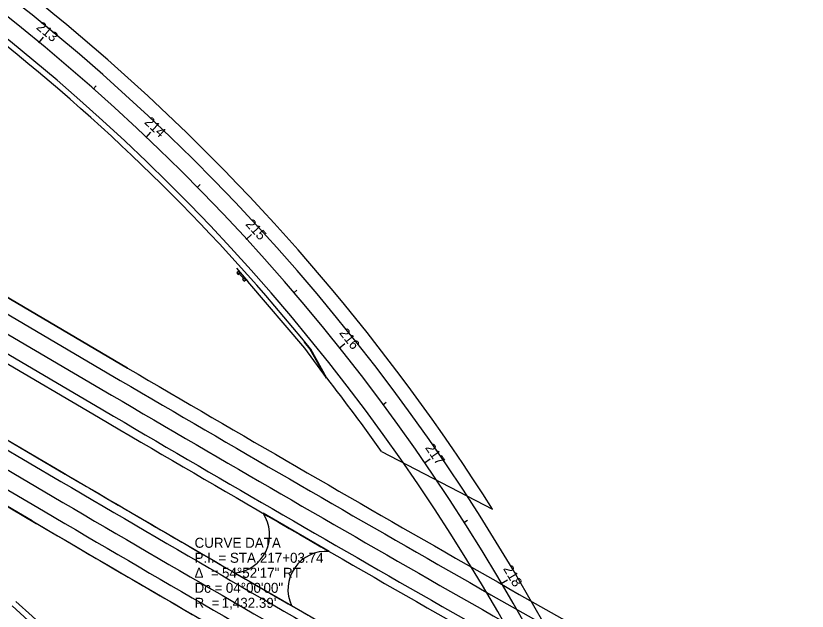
# Model space of a CAD drawing. Extents: x 76539 to 88870, y 518807 to 527554.
# Drawn here: x 87208 to 87761, y 522669 to 523086 of the extents above; entities that cross this region are included whole.
import ezdxf

# ---------------------------------------------------------------- set-up
doc = ezdxf.new("R2010")
doc.units = 0
for name, color, linetype in [('GE_P_Alignment_100_Curve_Data', 7, 'Continuous'), ('GE_P_Alignment_100_Stations', 7, 'Continuous'), ('PM_P_Edge_Line', 7, 'Continuous'), ('PM_P_Lane_Line', 7, 'Continuous'), ('PV_P_Shoulder', 7, 'Continuous'), ('RD_P_GR_Lt', 7, 'Continuous'), ('XS_P_Pavt_Surface', 7, 'Continuous')]:
    doc.layers.add(name, color=color, linetype=linetype)

msp = doc.modelspace()

# ---------------------------------------------------------------- linework, layer by layer
at = {"layer": 'GE_P_Alignment_100_Stations'}
for p, q in [((87224.3, 523066.94), (87227.48, 523070.8)), ((87262.32, 523034.48), (87264.31, 523036.72)), ((87299.19, 523000.71), (87302.64, 523004.34)), ((87334.86, 522965.67), (87337, 522967.78)), ((87369.29, 522929.41), (87372.97, 522932.79)), ((87402.43, 522891.98), (87404.71, 522893.93)), ((87434.24, 522853.4), (87438.15, 522856.52)), ((87464.68, 522813.75), (87467.1, 522815.53)), ((87493.73, 522773.05), (87497.85, 522775.88)), ((87521.33, 522731.36), (87523.86, 522732.98)), ((87547.47, 522688.74), (87551.77, 522691.28))]:
    msp.add_line(p, q, dxfattribs=at)
at = {"layer": 'PM_P_Edge_Line'}
for p, q in [((86028.65, 523566.61), (87281.21, 522830.81)), ((86016.49, 523545.92), (87269.05, 522810.12)), ((86962.35, 522923.05), (87239.68, 522760.13)), ((86950.19, 522902.35), (87227.53, 522739.44))]:
    msp.add_line(p, q, dxfattribs=at)
for centre, radius, start, end in [((86313.45, 521961.45), 1444.39, 9.23728, 64.10866), ((86313.45, 521961.45), 1444.39, 9.23728, 64.10866), ((86313.45, 521961.45), 1420.39, 9.24998, 64.10866), ((98861.51, 542544.07), 22862.98, 239.568441, 240.940285), ((98861.51, 542544.07), 22886.98, 239.568441, 240.940285), ((98861.51, 542544.07), 22944.95, 239.568441, 240.940516), ((98861.51, 542544.07), 22968.95, 239.568441, 240.940516), ((86249.47, 521595.47), 1440.6, 9.83522, 48.42092)]:
    msp.add_arc(centre, radius, start, end, dxfattribs=at)
at = {"layer": 'PM_P_Lane_Line'}
for p, q in [((86022.57, 523556.26), (87275.13, 522820.47)), ((86956.27, 522912.7), (87233.61, 522749.78))]:
    msp.add_line(p, q, dxfattribs=at)
for centre, radius, start, end in [((86313.45, 521961.45), 1432.72, 9.23728, 64.10866), ((98861.51, 542544.07), 22874.98, 239.568441, 240.940285), ((98861.51, 542544.07), 22956.95, 239.568441, 240.940516)]:
    msp.add_arc(centre, radius, start, end, dxfattribs=at)
at = {"layer": 'PV_P_Shoulder'}
for p, q in [((86033.71, 523575.23), (87286.27, 522839.43)), ((86013.45, 523540.74), (87266.01, 522804.95)), ((86965.39, 522928.22), (87242.72, 522765.3)), ((86945.13, 522893.73), (87222.46, 522730.81)), ((87409.82, 522857.4), (87410.22, 522857.7)), ((87414.19, 522852.82), (87425.45, 522832.61)), ((87425.04, 522832.33), (87425.45, 522832.61)), ((87427.16, 522711.16), (87380.97, 522737.86)), ((87361.24, 522696.16), (87400.87, 522673.25))]:
    msp.add_line(p, q, dxfattribs=at)
for points in [[(87409.82, 522857.4), (87413.78, 522852.53), (87425.02, 522832.37)], [(87425.45, 522832.61), (87414.19, 522852.82), (87410.21, 522857.71)]]:
    msp.add_lwpolyline(points, dxfattribs=at)
for centre, radius, start, end in [((86313.45, 521961.45), 1454.39, 32.40267, 64.10866), ((86313.45, 521961.45), 1416.39, 39.00003, 64.10866), ((98861.51, 542544.07), 22852.98, 239.568441, 240.940285), ((86313.09, 521963.9), 1411.39, 35.38209, 37.98821), ((98861.51, 542544.07), 22892.98, 239.568441, 240.940285), ((98861.51, 542544.07), 22938.95, 239.568441, 240.940516), ((87358.94, 522722.76), 26.7, 274.9311, 34.4368), ((98861.51, 542544.07), 22978.95, 239.568441, 240.940516), ((87425.07, 522684.54), 26.7, 85.4999, 205.0056), ((86249.47, 521595.47), 1444.6, 9.8228, 48.42092)]:
    msp.add_arc(centre, radius, start, end, dxfattribs=at)
at = {"layer": 'RD_P_GR_Lt'}
for p, q in [((87362.34, 522909.32), (87370.45, 522899.82)), ((87367.94, 522901.31), (87363.88, 522906.07))]:
    msp.add_line(p, q, dxfattribs=at)
for points in [[(87362.66, 522906.04), (87363.67, 522904.86), (87365.1, 522906.09), (87364.09, 522907.27)], [(87366.72, 522901.29), (87367.73, 522900.11), (87369.16, 522901.34), (87368.15, 522902.51)]]:
    msp.add_lwpolyline(points, close=True, dxfattribs=at)
msp.add_lwpolyline([(87425.45, 522832.61), (87410.25, 522853.38), (87370.45, 522899.82)], dxfattribs=at)
at = {"layer": 'XS_P_Pavt_Surface'}
for p, q in [((87286.27, 522839.43), (86033.71, 523575.23)), ((86013.45, 523540.74), (87266.01, 522804.95)), ((86962.55, 522929.89), (87239.85, 522766.99)), ((87219.55, 522732.53), (86942.25, 522895.42)), ((87463.8, 522781.13), (87541.4, 522740.81))]:
    msp.add_line(p, q, dxfattribs=at)
for centre, radius, start, end in [((86313.45, 521961.45), 1454.39, 32.40267, 64.10866), ((86313.45, 521961.45), 1416.39, 39.00003, 64.10866), ((98861.51, 542544.07), 22852.98, 239.568441, 240.940285), ((86313.09, 521963.9), 1411.39, 35.38209, 37.98821), ((98861.51, 542544.07), 22892.98, 239.568441, 240.940285), ((99004.35, 542793.24), 23226.15, 239.567729, 240.780111), ((99002.02, 542789.93), 23262.12, 239.568441, 240.931339), ((86249.46, 521595.47), 1444.6, 9.8228, 48.42092)]:
    msp.add_arc(centre, radius, start, end, dxfattribs=at)

# ---------------------------------------------------------------- texts
at = {"layer": 'GE_P_Alignment_100_Curve_Data'}
for s, p in [('CURVE DATA', (87333.1, 522713.72)), ('P.I. = STA. ', (87333.1, 522703.22)), ('217+03.74', (87378.77, 522703.22)), ('Δ  = ', (87333.1, 522692.72)), ('54°52\'17" RT', (87352.29, 522692.72)), ('Dc = ', (87333.1, 522682.22)), ('04°00\'00"', (87354.95, 522682.22)), ('R  = ', (87333.1, 522671.72)), ("1,432.39'", (87352.05, 522671.72))]:
    msp.add_text(s, height=7, dxfattribs=at).set_placement(p)
at = {"layer": 'GE_P_Alignment_100_Stations'}
for s, rotation, p in [('213', 320.5138, (87221.96, 523076.96)), ('214', 316.5138, (87297.56, 523010.87)), ('215', 312.5138, (87368.31, 522939.73)), ('216', 308.5138, (87433.9, 522863.87)), ('217', 304.5138, (87494.04, 522783.63)), ('218', 300.5138, (87548.62, 522699.1))]:
    msp.add_text(s, height=7, rotation=rotation, dxfattribs=at).set_placement(p)

doc.saveas('drawing.dxf')
